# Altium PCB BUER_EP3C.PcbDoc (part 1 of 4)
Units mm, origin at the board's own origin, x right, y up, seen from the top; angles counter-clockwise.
Board outline 150 x 80 mm, 2 copper layers (Top Layer, Bottom Layer), stack 1.571 mm thick; 295 components, 180 nets, 1344 pads, 488 vias.
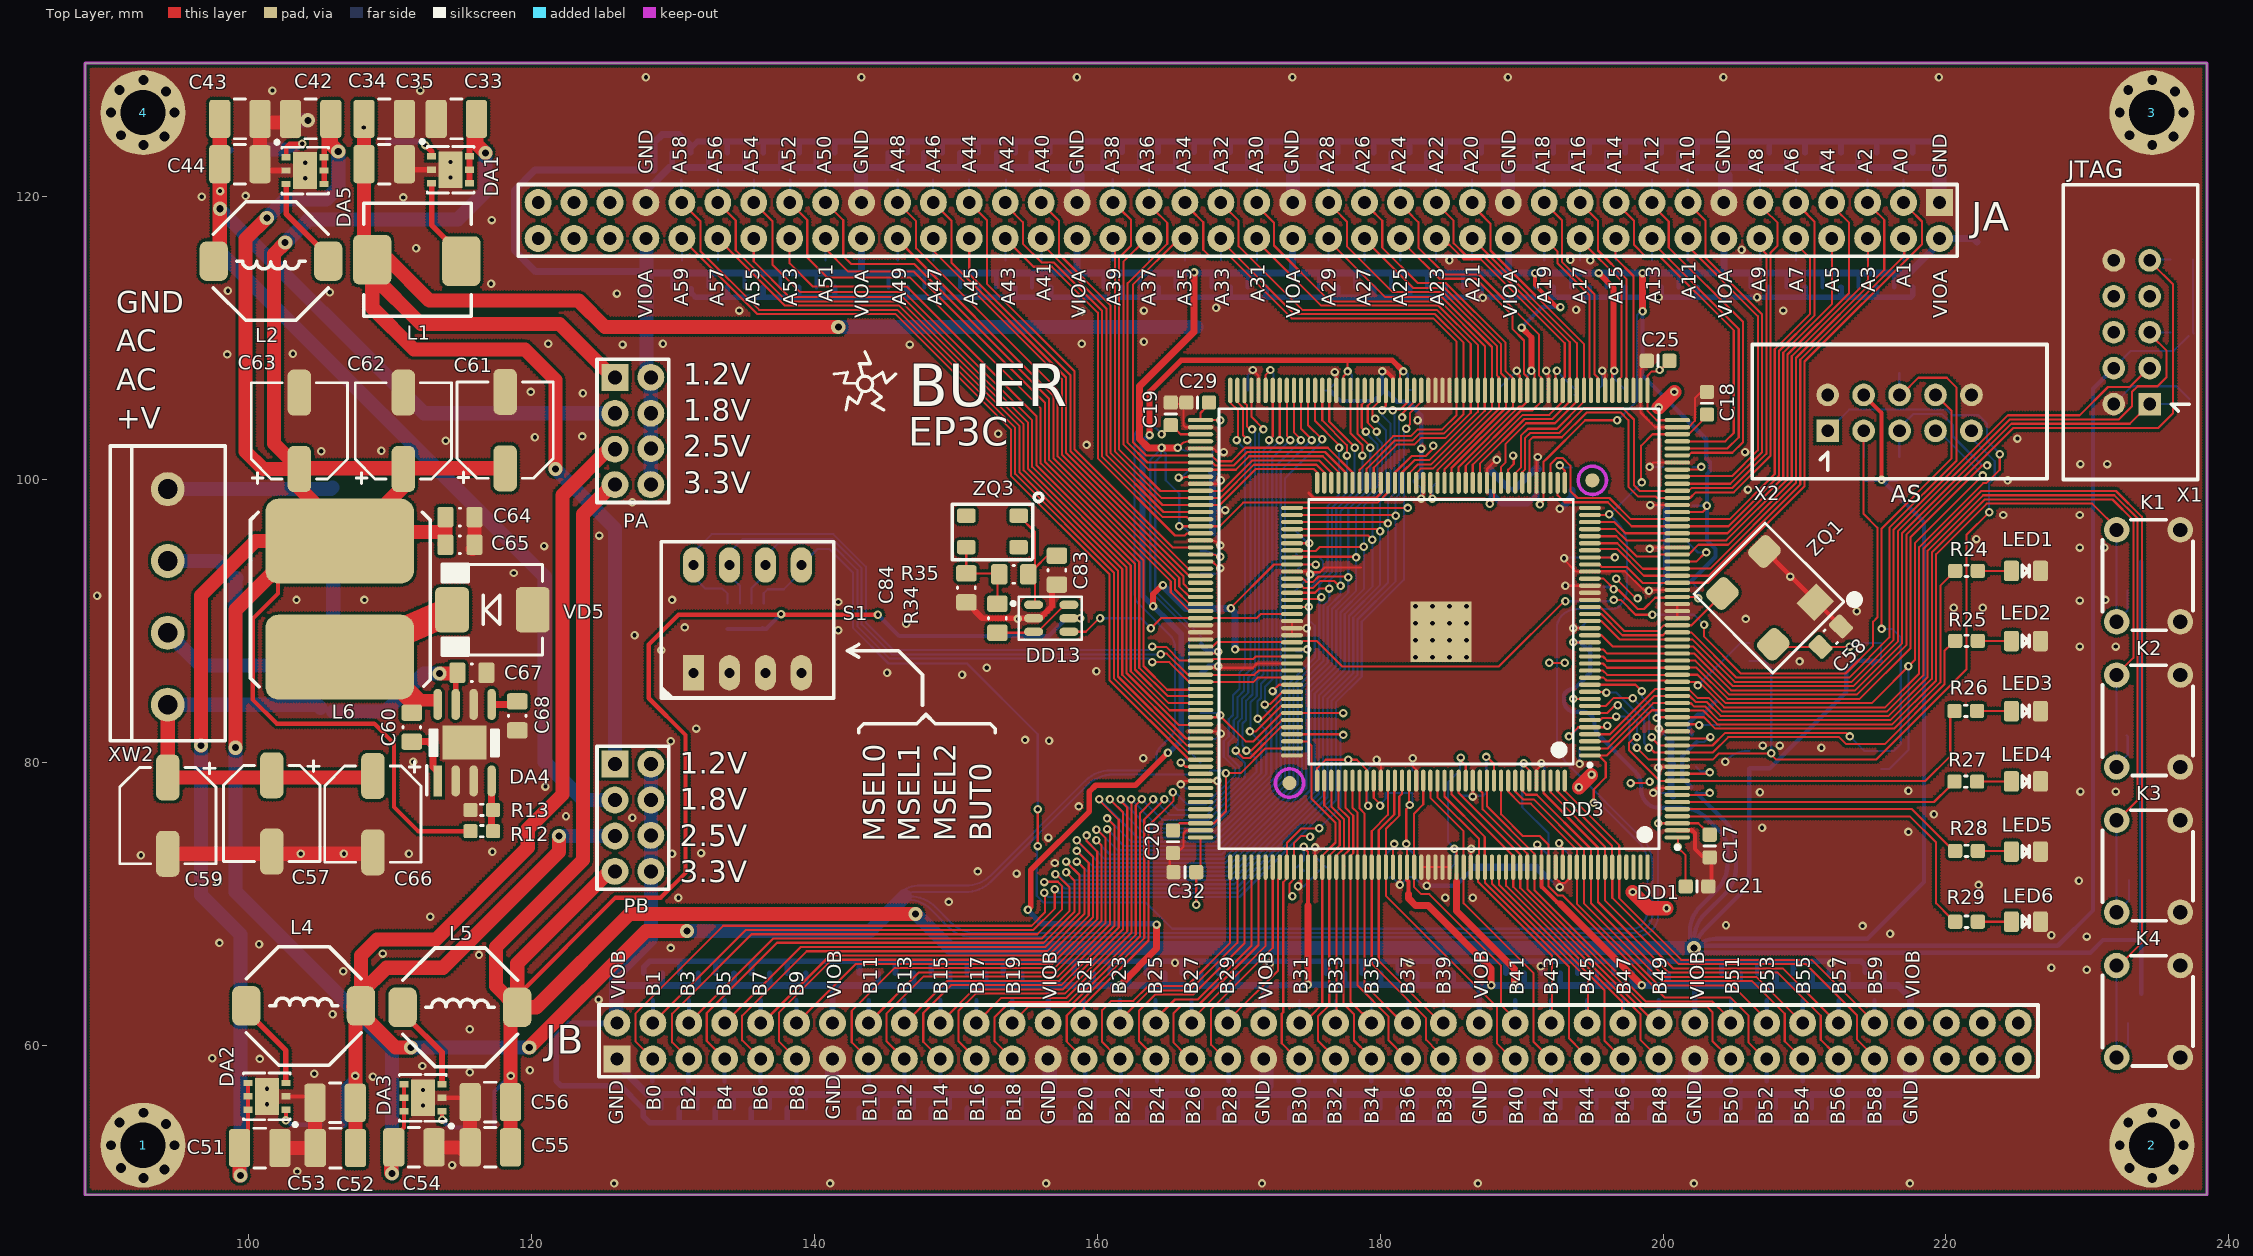
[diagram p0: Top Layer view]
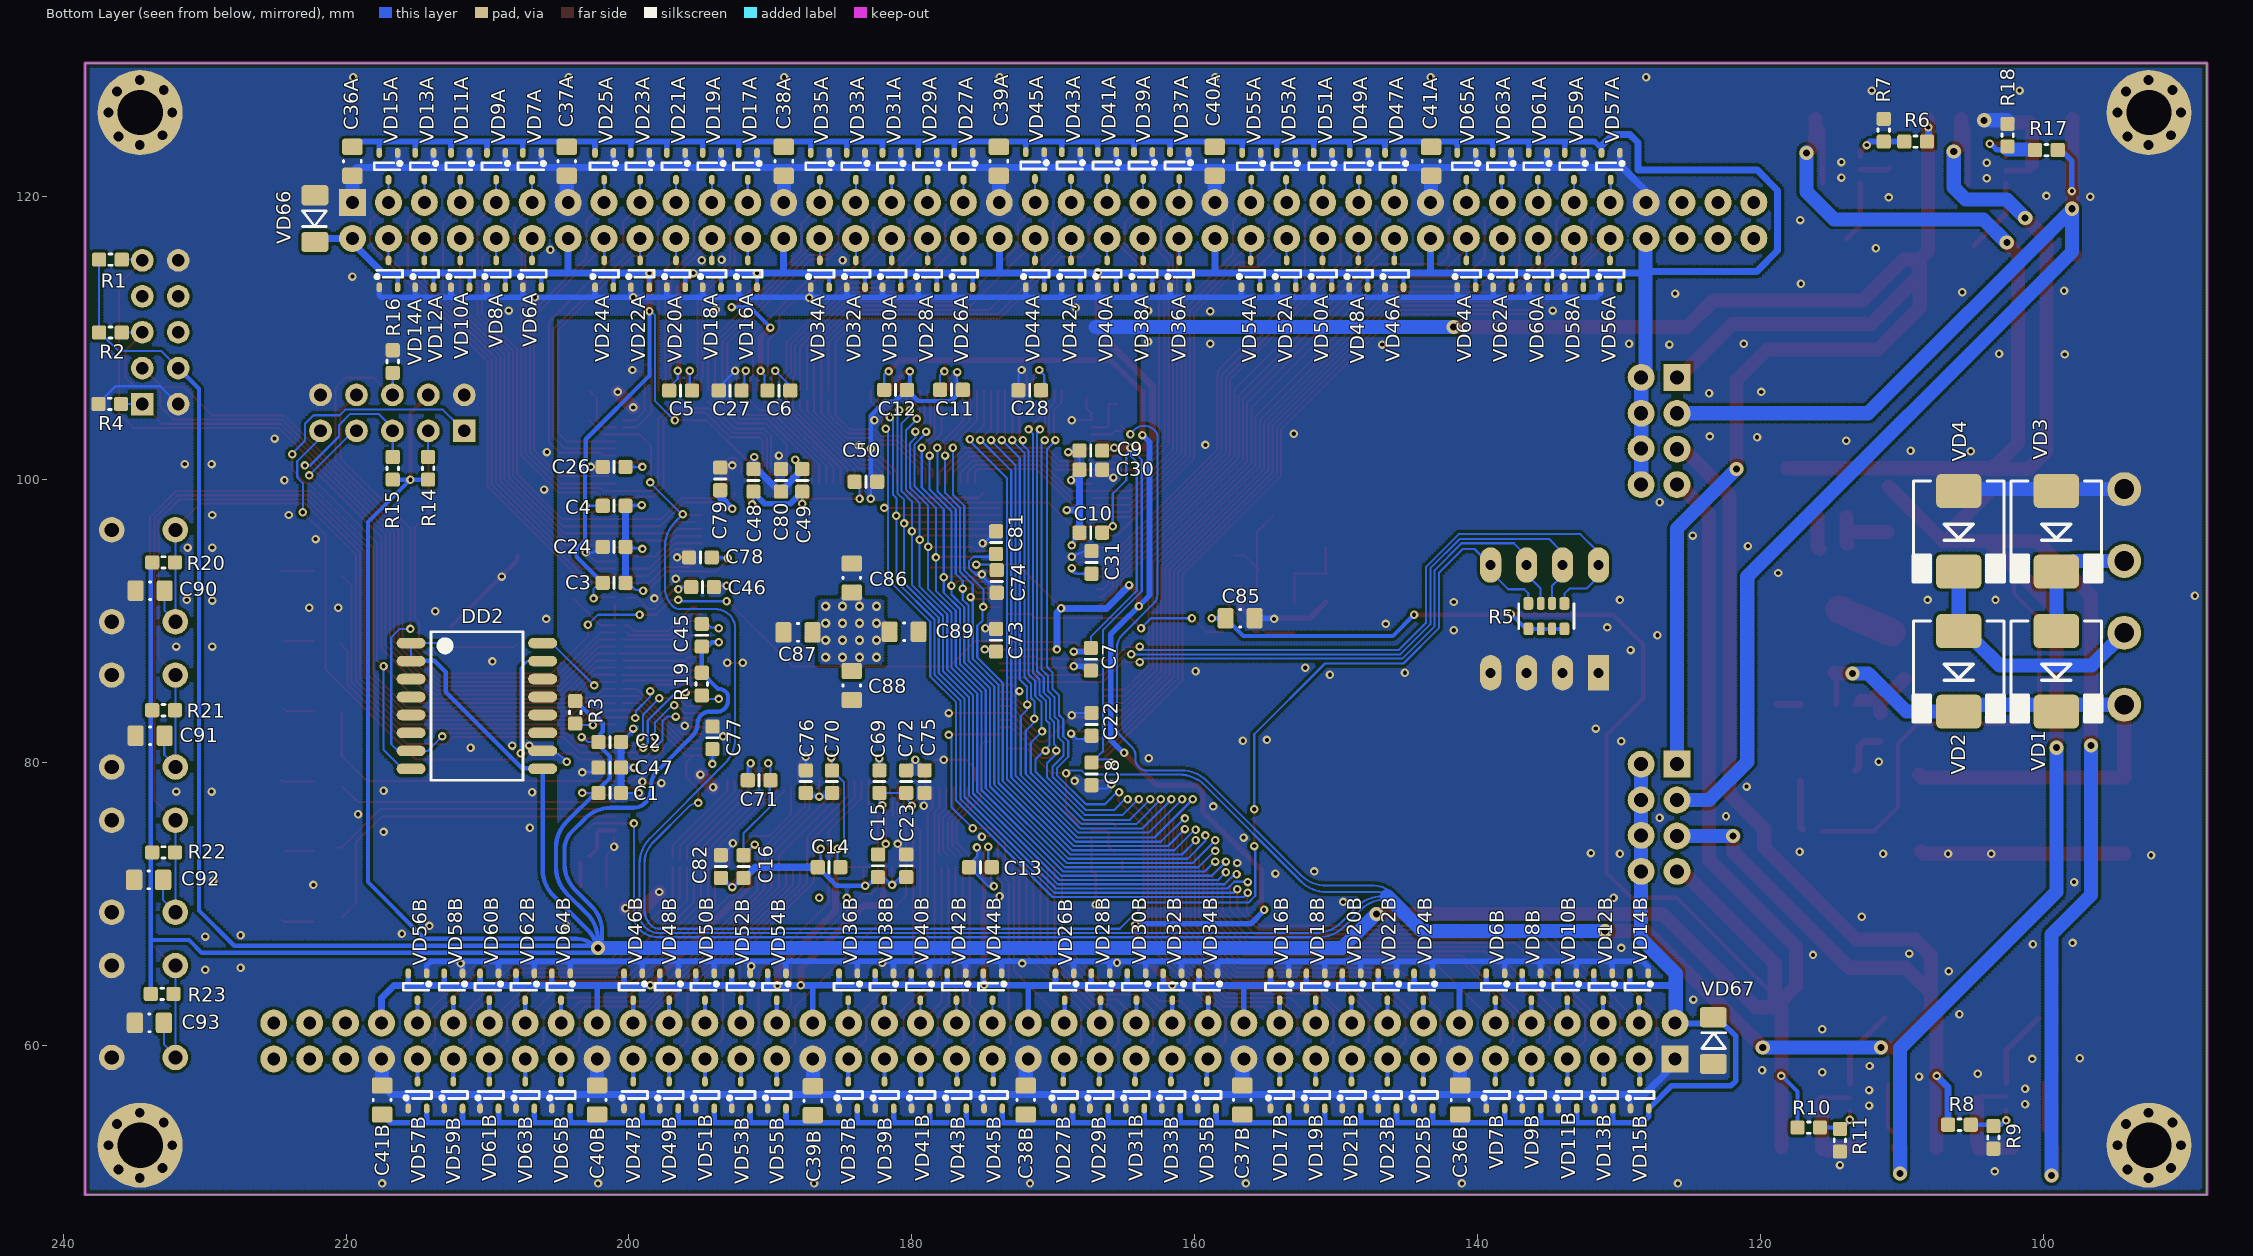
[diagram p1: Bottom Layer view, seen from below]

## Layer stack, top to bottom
Top Solder: solder mask 0.0102, Solder Resist, Dk 3.5
Top Layer: signal copper 0.0356
Dielectric1: core 1.5, FR-4, Dk 4.8
Bottom Layer: signal copper 0.0356
Bottom Solder: solder mask 0.0102, Solder Resist, Dk 3.5

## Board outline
88.45,49.45 88.45,129.45 238.45,129.45 238.45,49.45

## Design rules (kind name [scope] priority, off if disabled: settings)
Clearance Clearance_POLY [InPolygon] p1: gap=0.2
Clearance [All] p2: gap=0.15
ComponentClearance ComponentClearance_1 [InComponent('DD1') vs InComponent('DD3')] p1: gap=0 collisioncheckmode=3 verticalgap=0 showdistances=FALSE
ComponentClearance [All] p2: gap=0.254 collisioncheckmode=3 verticalgap=0.254 showdistances=FALSE
HoleSize [All] p1: absolutevalues=TRUE maxlimit=10 minlimit=0.3 maxpercent=80.000 minpercent=20.000
MinimumSolderMaskSliver MinimumSolderMaskSliver_1 [InComponent('1','2','3','4')] p1: minsoldermaskwidth=0
MinimumSolderMaskSliver [All] p2: minsoldermaskwidth=0.03
PlaneConnect [All] p1: planeconnectstyle=Direct reliefexpansion=0.508 reliefentries=4 reliefconductorwidth=0.254 reliefairgap=0.254
PolygonConnect [All] p1: connectstyle=Direct reliefconductorwidth=0.254 reliefentries=4 polygonreliefangle="90 Angle" airgapwidth=0.254
RoutingVias [All] p1: holewidth=0.5 width=1.3 viastyle="Through Hole" minholewidth=0.3 minwidth=0.6 maxholewidth=5 maxwidth=10
SilkToSilkClearance [All] p1: silktosilkclearance=0
SilkToSolderMaskClearance SilkscreenOverComponentPads [IsPad] p1: minsilkscreentomaskgap=0 clearancetoexposedcopper=TRUE
SolderMaskExpansion [All] p1: expansion=0.102
Width [All] p1: maxlimit=2 minlimit=0.15 preferedwidth=0.25
23 further rules are at their usual default settings.

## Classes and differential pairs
net class LED[0..5]: LED0 LED1 LED2 LED3 LED4 LED5
component class F: C42 C43 C44 DA5 L2 R17 R18
component class S: C60 C61 C62 C63 C64 C65 C66 C67 C68 DA4 L6 R12 R13 VD5
component class D: C33 C34 C35 DA1 L1 R6 R7
component class H: C54 C55 C56 DA3 L5 R10 R11
component class G: C51 C52 C53 DA2 L4 R8 R9
component class 0: DD1 R3
component class Main: 1 2 3 4 C58 C83 C84 C85 C90 C91 C92 C93 DD2 DD13 K1 K2 K3 K4 LED1 LED2 LED3 LED4 LED5 LED6 R1 R2 R4 R5 R14 R15 R16 R20 R21 R22 R23 R24 R25 R26 R27 R28 R29 R34 R35 S1 X1 X2 ZQ1 ZQ3
component class 3: C1 C2 C3 C4 C5 C6 C7 C8 C9 C10 C11 C12 C13 C14 C15 C16 C17 C18 C19 C20 C21 C22 C23 C24 C25 C26 C27 C28 C29 C30 C31 C32 C45 C46 C47 C48 C49 C50 C57 C59 C69 C70 C71 C72 C73 C74 C75 C76 C77 C78 C79 C80 C81 C82 C86 C87 C88 C89 PA PB VD1 VD2 VD3 VD4 XW2
component class A: JA VD66
net class A[0..59]: A0 A1 A2 A3 A4 A5 A6 A7 A8 A9 A10 A11 A12 A13 A14 A15 A16 A17 A18 A19 A20 A21 A22 A23 A24 A25 A26 A27 A28 A29 A30 A31 A32 A33 A34 A35 A36 A37 A38 A39 A40 A41 A42 A43 A44 A45 A46 A47 A48 A49 A50 A51 A52 A53 A54 A55 A56 A57 A58 A59
component class B: JB VD67
net class B[0..59]: B0 B1 B2 B3 B4 B5 B6 B7 B8 B9 B10 B11 B12 B13 B14 B15 B16 B17 B18 B19 B20 B21 B22 B23 B24 B25 B26 B27 B28 B29 B30 B31 B32 B33 B34 B35 B36 B37 B38 B39 B40 B41 B42 B43 B44 B45 B46 B47 B48 B49 B50 B51 B52 B53 B54 B55 B56 B57 B58 B59
channel class "10pin ESD protect_1": 11 12
channel class "10pin ESD protect_2": 21 22
channel class "10pin ESD protect_3": 31 32
channel class "10pin ESD protect_4": 41 42
channel class "10pin ESD protect_5": 51 52
channel class "10pin ESD protect_6": 61 62
component class 1A: C36A VD6A VD7A VD8A VD9A VD10A VD11A VD12A VD13A VD14A VD15A
component class 1B: C36B VD6B VD7B VD8B VD9B VD10B VD11B VD12B VD13B VD14B VD15B
component class 2A: C37A VD16A VD17A VD18A VD19A VD20A VD21A VD22A VD23A VD24A VD25A
component class 2B: C37B VD16B VD17B VD18B VD19B VD20B VD21B VD22B VD23B VD24B VD25B
component class 3A: C38A VD26A VD27A VD28A VD29A VD30A VD31A VD32A VD33A VD34A VD35A
component class 3B: C38B VD26B VD27B VD28B VD29B VD30B VD31B VD32B VD33B VD34B VD35B
component class 4A: C39A VD36A VD37A VD38A VD39A VD40A VD41A VD42A VD43A VD44A VD45A
component class 4B: C39B VD36B VD37B VD38B VD39B VD40B VD41B VD42B VD43B VD44B VD45B
component class 5A: C40A VD46A VD47A VD48A VD49A VD50A VD51A VD52A VD53A VD54A VD55A
component class 5B: C40B VD46B VD47B VD48B VD49B VD50B VD51B VD52B VD53B VD54B VD55B
component class 6A: C41A VD56A VD57A VD58A VD59A VD60A VD61A VD62A VD63A VD64A VD65A
component class 6B: C41B VD56B VD57B VD58B VD59B VD60B VD61B VD62B VD63B VD64B VD65B
net class MSEL[0..2]: MSEL0 MSEL1 MSEL2
component class 1: DD3 R19
net class BUT[0..3]: BUT0 BUT1 BUT2 BUT3

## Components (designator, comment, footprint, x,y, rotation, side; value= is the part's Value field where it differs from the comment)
1 "M3" M3 92.581,52.947 r90 top
2 "M3" M3 234.581,52.947 r90 top
3 "M3" M3 234.581,125.947 r90 top
4 "M3" M3 92.581,125.947 r90 top
C1 "100нФ 50 В 10% 0603 X7R" C0603 201.35,77.85 r180 bottom
C2 "100нФ 50 В 10% 0603 X7R" C0603 201.35,81.45 r180 bottom
C3 "100нФ 50 В 10% 0603 X7R" C0603 201.05,92.7 r180 bottom
C4 "100нФ 50 В 10% 0603 X7R" C0603 201.05,98.15 r180 bottom
C5 "100нФ 50 В 10% 0603 X7R" C0603 196.35,106.3 r180 bottom
C6 "100нФ 50 В 10% 0603 X7R" C0603 189.4,106.3 r180 bottom
C7 "100нФ 50 В 10% 0603 X7R" C0603 167.35,87.3 r270 bottom
C8 "100нФ 50 В 10% 0603 X7R" C0603 167.3,79.2 r270 bottom
C9 "100нФ 50 В 10% 0603 X7R" C0603 167.35,102.05 r0 bottom
C10 "100нФ 50 В 10% 0603 X7R" C0603 167.35,96.25 r0 bottom
C11 "100нФ 50 В 10% 0603 X7R" C0603 177.2,106.35 r180 bottom
C12 "100нФ 50 В 10% 0603 X7R" C0603 181.152,106.343 r180 bottom
C13 "100нФ 50 В 10% 0603 X7R" C0603 175.15,72.6 r0 bottom
C14 "100нФ 50 В 10% 0603 X7R" C0603 185.85,72.6 r0 bottom
C15 "100нФ 50 В 10% 0603 X7R" C0603 182.4,72.7 r270 bottom
C16 "100нФ 50 В 10% 0603 X7R" C0603 191.9,72.65 r270 bottom
C17 "100нФ 50 В 10% 0603 X7R" C0603 203.3,74.1 r270 top
C18 "100нФ 50 В 10% 0603 X7R" C0603 203.1,105.4 r90 top
C19 "100нФ 50 В 10% 0603 X7R" C0603 165.2,104.65 r90 top
C20 "100нФ 50 В 10% 0603 X7R" C0603 165.35,74.4 r270 top
C21 "100нФ 50 В 10% 0603 X7R" C0603 202.4,71.25 r0 top
C22 "100нФ 50 В 10% 0603 X7R" C0603 167.3,82.7 r270 bottom
C23 "100нФ 50 В 10% 0603 X7R" C0603 180.4,72.7 r270 bottom
C24 "100нФ 50 В 10% 0603 X7R" C0603 201.05,95.25 r180 bottom
C25 "100нФ 50 В 10% 0603 X7R" C0603 199.65,108.4 r180 top
C26 "100нФ 50 В 10% 0603 X7R" C0603 201.05,100.9 r180 bottom
C27 "100нФ 50 В 10% 0603 X7R" C0603 192.85,106.3 r180 bottom
C28 "100нФ 50 В 10% 0603 X7R" C0603 171.67,106.315 r180 bottom
C29 "100нФ 50 В 10% 0603 X7R" C0603 167.1,105.45 r180 top
C30 "100нФ 50 В 10% 0603 X7R" C0603 167.35,100.7 r0 bottom
C31 "100нФ 50 В 10% 0603 X7R" C0603 167.3,94.15 r270 bottom
C32 "100нФ 50 В 10% 0603 X7R" C0603 166.2,72.25 r180 top
C33 "22 мкФ 20% 16 В 1210 X7R" C1210 114.7,125.5 r180 top
C34 "22 мкФ 20% 16 В 1210 X7R" C1210 109.6,125.5 r0 top
C35 "22 мкФ 20% 16 В 1210 X7R" C1210 109.6,122.3 r0 top
C36A "470нФ 10% 50 В" C0805 219.55,122.5 r270 bottom (schematic designator C36)
C36B "470нФ 10% 50 В" C0805 141.25,56.15 r90 bottom (schematic designator C36)
C37A "470нФ 10% 50 В" C0805 204.4,122.5 r270 bottom (schematic designator C37)
C37B "470нФ 10% 50 В" C0805 156.65,56.15 r90 bottom (schematic designator C37)
C38A "470нФ 10% 50 В" C0805 189.05,122.5 r270 bottom (schematic designator C38)
C38B "470нФ 10% 50 В" C0805 171.95,56.15 r90 bottom (schematic designator C38)
C39A "470нФ 10% 50 В" C0805 173.85,122.5 r270 bottom (schematic designator C39)
C39B "470нФ 10% 50 В" C0805 187,56.1 r90 bottom (schematic designator C39)
C40A "470нФ 10% 50 В" C0805 158.6,122.5 r270 bottom (schematic designator C40)
C40B "470нФ 10% 50 В" C0805 202.25,56.15 r90 bottom (schematic designator C40)
C41A "470нФ 10% 50 В" C0805 143.3,122.5 r270 bottom (schematic designator C41)
C41B "470нФ 10% 50 В" C0805 217.45,56.15 r90 bottom (schematic designator C41)
C42 "22 мкФ 20% 16 В 1210 X7R" C1210 104.4,125.5 r180 top
C43 "22 мкФ 20% 16 В 1210 X7R" C1210 99.4,125.5 r0 top
C44 "22 мкФ 20% 16 В 1210 X7R" C1210 99.4,122.3 r0 top
C45 "100нФ 50 В 10% 0603 X7R" C0603 194.85,89 r90 bottom
C46 "100нФ 50 В 10% 0603 X7R" C0603 194.8,92.4 r180 bottom
C47 "100нФ 50 В 10% 0603 X7R" C0603 201.35,79.65 r180 bottom
C48 "100нФ 50 В 10% 0603 X7R" C0603 191.2,99.95 r90 bottom
C49 "100нФ 50 В 10% 0603 X7R" C0603 187.75,99.95 r90 bottom
C50 "100нФ 50 В 10% 0603 X7R" C0603 183.25,99.85 r180 bottom
C51 "22 мкФ 20% 16 В 1210 X7R" C1210 100.8,52.75 r0 top
C52 "22 мкФ 20% 16 В 1210 X7R" C1210 106.125,55.95 r180 top
C53 "22 мкФ 20% 16 В 1210 X7R" C1210 106.15,52.75 r180 top
C54 "22 мкФ 20% 16 В 1210 X7R" C1210 111.7,52.8 r0 top
C55 "22 мкФ 20% 16 В 1210 X7R" C1210 117.101,52.8 r180 top
C56 "22 мкФ 20% 16 В 1210 X7R" C1210 117.1,56 r180 top
C57 "100мкФ 35В 6.3x8" ELCAP_SMD_6.3x8 101.65,76.4 r270 top
C58 "470нФ 10% 50 В" C0805 211.85,88.9 r45 top
C59 "100мкФ 35В 6.3x8" ELCAP_SMD_6.3x8 94.3,76.25 r270 top
C60 "10нФ 10% 50 В" C0805 111.55,82.5 r90 top
C61 "220мкФ 16В 6.3x8" ELCAP_SMD_6.3x8 118.15,103.5 r90 top
C62 "220мкФ 16В 6.3x8" ELCAP_SMD_6.3x8 110.95,103.45 r90 top
C63 "220мкФ 16В 6.3x8" ELCAP_SMD_6.3x8 103.6,103.45 r90 top
C64 "470нФ 10% 50 В" C0805 114.95,97.35 r0 top
C65 "10нФ 10% 50 В" C0805 114.95,95.4 r0 top
C66 "100мкФ 35В 6.3x8" ELCAP_SMD_6.3x8 108.8,76.35 r270 top
C67 "470нФ 10% 50 В" C0805 115.8,86.35 r0 top
C68 "470нФ 10% 50 В" C0805 119,83.3 r270 top
C69 "100нФ 50 В 10% 0603 X7R" C0603 182.3,78.65 r90 bottom
C70 "100нФ 50 В 10% 0603 X7R" C0603 185.65,78.65 r270 bottom
C71 "100нФ 50 В 10% 0603 X7R" C0603 190.8,78.75 r0 bottom
C72 "100нФ 50 В 10% 0603 X7R" C0603 180.4,78.65 r90 bottom
C73 "100нФ 50 В 10% 0603 X7R" C0603 174.05,88.65 r90 bottom
C74 "100нФ 50 В 10% 0603 X7R" C0603 174,92.8 r270 bottom
C75 "100нФ 50 В 10% 0603 X7R" C0603 179.1,78.65 r90 bottom
C76 "100нФ 50 В 10% 0603 X7R" C0603 187.5,78.65 r270 bottom
C77 "100нФ 50 В 10% 0603 X7R" C0603 194.1,81.75 r270 bottom
C78 "100нФ 50 В 10% 0603 X7R" C0603 194.95,94.5 r180 bottom
C79 "100нФ 50 В 10% 0603 X7R" C0603 193.55,100.05 r270 bottom
C80 "100нФ 50 В 10% 0603 X7R" C0603 189.25,99.95 r270 bottom
C81 "100нФ 50 В 10% 0603 X7R" C0603 174.05,95.55 r270 bottom
C82 "100нФ 50 В 10% 0603 X7R" C0603 193.5,72.65 r270 bottom
C83 "27пФ  5%  50В 0805 NPO" C0805 157.15,93.6 r270 top
C84 "27пФ  5%  50В 0805 NPO" C0805 150.75,92.35 r270 top
C85 "470нФ 10% 50 В" C0805 156.8,90.2 r180 bottom
C86 "470нФ 10% 50 В" C0805 184.25,93.05 r270 bottom
C87 "470нФ 10% 50 В" C0805 188.05,89.2 r180 bottom
C88 "470нФ 10% 50 В" C0805 184.25,85.45 r90 bottom
C89 "470нФ 10% 50 В" C0805 180.55,89.25 r0 bottom
C90 "10нФ 10% 50 В" C0805 233.85,92.15 r0 bottom
C91 "10нФ 10% 50 В" C0805 233.85,81.9 r0 bottom
C92 "10нФ 10% 50 В" C0805 233.95,71.7 r0 bottom
C93 "10нФ 10% 50 В" C0805 233.9,61.6 r0 bottom
DA1 "NCP1597A" DFN6 114.29,121.9 r270 top
DA2 "NCP1597A" DFN6 101.31,56.4 r90 top
DA3 "NCP1597A" DFN6 112.34,56.3 r90 top
DA4 "TPS5450DDA" HSOP8 115.285,81.405 r90 top
DA5 "NCP1597A" DFN6 104.01,121.85 r270 top
DD1 "EP3C16Q240C8N" PQFP240_N 184.156,89.457 r180 top
DD2 "EPCS16SI16N" SO-16W 210.75,84 r270 bottom
DD3 "EP3C10E144C8" EQFP-144 184.3,89.25 r180 top
DD13 "74LVC2G04" SOT-23-6 156.75,90.2 r0 top
JA "PLD-80" "HEADER 2X40" 219.54,119.59 r180 top
JB "PLD-80" "HEADER 2X40" 126.05,59.05 r0 top
K1 "SWT-2/5 (0650HIM-160G-G)" SWT-2/5 234.35,93.25 r270 top
K2 "SWT-2/5 (0650HIM-160G-G)" SWT-2/5 234.35,82.983 r270 top
K3 "SWT-2/5 (0650HIM-160G-G)" SWT-2/5 234.35,72.717 r270 top
K4 "SWT-2/5 (0650HIM-160G-G)" SWT-2/5 234.35,62.45 r270 top
L1 "DR73-3R3-R" DR73 111.95,115.45 r180 top
L2 "CDRH8D43NP-6R8NC" CDRH8D43 105.65,115.45 r180 top
L4 "CDRH8D43NP-6R8NC" CDRH8D43 99.85,62.8 r0 top
L5 "CDRH8D43NP-6R8NC" CDRH8D43 110.9,62.7 r0 top
L6 "DR127-150-R" DR127 106.55,91.55 r90 top
LED1 "FYLS-0805UWC" LED0805W 225.65,93.55 r0 top
LED2 "FYLS-0805UWC" LED0805W 225.65,88.59 r0 top
LED3 "FYLS-0805UWC" LED0805W 225.65,83.63 r0 top
LED4 "FYLS-0805UWC" LED0805W 225.65,78.67 r0 top
LED5 "FYLS-0805UWC" LED0805W 225.65,73.71 r0 top
LED6 "FYLS-0805UWC" LED0805W 225.65,68.751 r0 top
PA "PLD-8" "HEADER 2X4" 128.45,107.23 r270 top
PB "PLD-8" "HEADER 2X4" 128.45,79.89 r270 top
R1 "10 кОм 0603 5%" R0603 236.65,115.55 r0 bottom
R2 "10 кОм 0603 5%" R0603 236.65,110.4 r0 bottom
R3 "10 кОм 0603 5%" R0603 203.8,83.55 r90 bottom
R4 "10 кОм 0603 5%" R0603 236.7,105.35 r0 bottom
R5 "2.2 кОм 4D03" 4D03 135.15,90.35 r270 bottom
R6 "1.0 кОм 0603 5%" R0603 109.05,123.9 r180 bottom
R7 "2.0 кОм 0603 5%" R0603 111.3,124.7 r270 bottom
R8 "5.1 кОм 0603 5%" R0603 105.95,54.4 r0 bottom
R9 "2.4 кОм 0603 5%" R0603 103.55,53.5 r90 bottom
R10 "7.5 кОм 0603 5%" R0603 116.6,54.2 r0 bottom
R11 "2.4 кОм 0603 5%" R0603 114.4,53.3 r90 bottom
R12 "6.8 кОм 0603 5%" R0603 116.5,75.15 r180 top
R13 "2.2 кОм 0603 5%" R0603 116.5,76.65 r0 top
R14 "10 кОм 0603 5%" R0603 214.2,100.8 r270 bottom
R15 "10 кОм 0603 5%" R0603 216.7,100.8 r270 bottom
R16 "10 кОм 0603 5%" R0603 216.7,108.35 r270 bottom
R17 "1.5 кОм 0603 5%" R0603 99.8,123.3 r180 bottom
R18 "1.2 кОм 0603 5%" R0603 102.55,124.35 r270 bottom
R19 "10 кОм 0603 5%" R0603 194.85,85.55 r90 bottom
R20 "1.0 кОм 0603 5%" R0603 232.9,94.15 r0 bottom
R21 "1.0 кОм 0603 5%" R0603 232.9,83.7 r0 bottom
R22 "1.0 кОм 0603 5%" R0603 232.9,73.65 r0 bottom
R23 "1.0 кОм 0603 5%" R0603 233,63.65 r0 bottom
R24 "1.0 кОм 0603 5%" R0603 221.45,93.55 r180 top
R25 "1.0 кОм 0603 5%" R0603 221.45,88.6 r180 top
R26 "1.0 кОм 0603 5%" R0603 221.4,83.65 r180 top
R27 "1.0 кОм 0603 5%" R0603 221.4,78.65 r180 top
R28 "1.0 кОм 0603 5%" R0603 221.45,73.75 r180 top
R29 "1.0 кОм 0603 5%" R0603 221.45,68.75 r180 top
R34 "200 Ом 0805 5%" R0805 152.95,90.2 r270 top
R35 "3.9 МОм 0805 5%" R0805 154.1,93.3 r180 top
S1 "SWD1-4" DIPSW-4 135.275,89.771 r0 top
VD1 "MBRS540T3G" "DO-214AB (SMC)" 99.1,86.45 r270 bottom
VD2 "MBRS540T3G" "DO-214AB (SMC)" 106,86.45 r270 bottom
VD3 "MBRS540T3G" "DO-214AB (SMC)" 99.1,96.35 r270 bottom
VD4 "MBRS540T3G" "DO-214AB (SMC)" 106,96.35 r270 bottom
VD5 "MBRS540T3G" "DO-214AB (SMC)" 117.25,90.8 r180 top
VD6A "BAT54SWT1G" SC-70 206.85,114.55 r90 bottom (schematic designator VD6)
VD6B "BAT54SWT1G" SC-70 138.75,64.15 r270 bottom (schematic designator VD6)
VD7A "BAT54SWT1G" SC-70 206.85,122.15 r270 bottom (schematic designator VD7)
VD7B "BAT54SWT1G" SC-70 138.75,56.5 r90 bottom (schematic designator VD7)
VD8A "BAT54SWT1G" SC-70 209.387,114.55 r90 bottom (schematic designator VD8)
VD8B "BAT54SWT1G" SC-70 136.212,64.15 r270 bottom (schematic designator VD8)
VD9A "BAT54SWT1G" SC-70 209.387,122.15 r270 bottom (schematic designator VD9)
VD9B "BAT54SWT1G" SC-70 136.2,56.5 r90 bottom (schematic designator VD9)
VD10A "BAT54SWT1G" SC-70 211.925,114.55 r90 bottom (schematic designator VD10)
VD10B "BAT54SWT1G" SC-70 133.675,64.15 r270 bottom (schematic designator VD10)
VD11A "BAT54SWT1G" SC-70 211.925,122.15 r270 bottom (schematic designator VD11)
VD11B "BAT54SWT1G" SC-70 133.65,56.5 r90 bottom (schematic designator VD11)
VD12A "BAT54SWT1G" SC-70 214.462,114.55 r90 bottom (schematic designator VD12)
VD12B "BAT54SWT1G" SC-70 131.137,64.15 r270 bottom (schematic designator VD12)
VD13A "BAT54SWT1G" SC-70 214.462,122.15 r270 bottom (schematic designator VD13)
VD13B "BAT54SWT1G" SC-70 131.1,56.5 r90 bottom (schematic designator VD13)
VD14A "BAT54SWT1G" SC-70 217,114.55 r90 bottom (schematic designator VD14)
VD14B "BAT54SWT1G" SC-70 128.6,64.15 r270 bottom (schematic designator VD14)
VD15A "BAT54SWT1G" SC-70 217,122.15 r270 bottom (schematic designator VD15)
VD15B "BAT54SWT1G" SC-70 128.55,56.5 r90 bottom (schematic designator VD15)
VD16A "BAT54SWT1G" SC-70 191.6,114.55 r90 bottom (schematic designator VD16)
VD16B "BAT54SWT1G" SC-70 154,64.15 r270 bottom (schematic designator VD16)
VD17A "BAT54SWT1G" SC-70 191.6,122.15 r270 bottom (schematic designator VD17)
VD17B "BAT54SWT1G" SC-70 154,56.5 r90 bottom (schematic designator VD17)
VD18A "BAT54SWT1G" SC-70 194.137,114.55 r90 bottom (schematic designator VD18)
VD18B "BAT54SWT1G" SC-70 151.463,64.15 r270 bottom (schematic designator VD18)
VD19A "BAT54SWT1G" SC-70 194.137,122.15 r270 bottom (schematic designator VD19)
VD19B "BAT54SWT1G" SC-70 151.462,56.5 r90 bottom (schematic designator VD19)
VD20A "BAT54SWT1G" SC-70 196.675,114.55 r90 bottom (schematic designator VD20)
VD20B "BAT54SWT1G" SC-70 148.925,64.15 r270 bottom (schematic designator VD20)
VD21A "BAT54SWT1G" SC-70 196.675,122.15 r270 bottom (schematic designator VD21)
VD21B "BAT54SWT1G" SC-70 148.925,56.5 r90 bottom (schematic designator VD21)
VD22A "BAT54SWT1G" SC-70 199.212,114.55 r90 bottom (schematic designator VD22)
VD22B "BAT54SWT1G" SC-70 146.387,64.15 r270 bottom (schematic designator VD22)
VD23A "BAT54SWT1G" SC-70 199.212,122.15 r270 bottom (schematic designator VD23)
VD23B "BAT54SWT1G" SC-70 146.387,56.5 r90 bottom (schematic designator VD23)
VD24A "BAT54SWT1G" SC-70 201.75,114.55 r90 bottom (schematic designator VD24)
VD24B "BAT54SWT1G" SC-70 143.85,64.15 r270 bottom (schematic designator VD24)
VD25A "BAT54SWT1G" SC-70 201.75,122.15 r270 bottom (schematic designator VD25)
VD25B "BAT54SWT1G" SC-70 143.85,56.5 r90 bottom (schematic designator VD25)
VD26A "BAT54SWT1G" SC-70 176.35,114.55 r90 bottom (schematic designator VD26)
VD26B "BAT54SWT1G" SC-70 169.2,64.15 r270 bottom (schematic designator VD26)
VD27A "BAT54SWT1G" SC-70 176.35,122.15 r270 bottom (schematic designator VD27)
VD27B "BAT54SWT1G" SC-70 169.3,56.5 r90 bottom (schematic designator VD27)
VD28A "BAT54SWT1G" SC-70 178.887,114.55 r90 bottom (schematic designator VD28)
VD28B "BAT54SWT1G" SC-70 166.662,64.15 r270 bottom (schematic designator VD28)
VD29A "BAT54SWT1G" SC-70 178.887,122.15 r270 bottom (schematic designator VD29)
VD29B "BAT54SWT1G" SC-70 166.762,56.5 r90 bottom (schematic designator VD29)
VD30A "BAT54SWT1G" SC-70 181.425,114.55 r90 bottom (schematic designator VD30)
VD30B "BAT54SWT1G" SC-70 164.125,64.15 r270 bottom (schematic designator VD30)
VD31A "BAT54SWT1G" SC-70 181.425,122.15 r270 bottom (schematic designator VD31)
VD31B "BAT54SWT1G" SC-70 164.225,56.5 r90 bottom (schematic designator VD31)
VD32A "BAT54SWT1G" SC-70 183.962,114.55 r90 bottom (schematic designator VD32)
VD32B "BAT54SWT1G" SC-70 161.588,64.15 r270 bottom (schematic designator VD32)
VD33A "BAT54SWT1G" SC-70 183.962,122.15 r270 bottom (schematic designator VD33)
VD33B "BAT54SWT1G" SC-70 161.687,56.5 r90 bottom (schematic designator VD33)
VD34A "BAT54SWT1G" SC-70 186.5,114.55 r90 bottom (schematic designator VD34)
VD34B "BAT54SWT1G" SC-70 159.05,64.15 r270 bottom (schematic designator VD34)
VD35A "BAT54SWT1G" SC-70 186.5,122.15 r270 bottom (schematic designator VD35)
VD35B "BAT54SWT1G" SC-70 159.15,56.5 r90 bottom (schematic designator VD35)
VD36A "BAT54SWT1G" SC-70 161.1,114.55 r90 bottom (schematic designator VD36)
VD36B "BAT54SWT1G" SC-70 184.5,64.15 r270 bottom (schematic designator VD36)
VD37A "BAT54SWT1G" SC-70 161.1,122.2 r270 bottom (schematic designator VD37)
VD37B "BAT54SWT1G" SC-70 184.5,56.5 r90 bottom (schematic designator VD37)
VD38A "BAT54SWT1G" SC-70 163.65,114.55 r90 bottom (schematic designator VD38)
VD38B "BAT54SWT1G" SC-70 181.95,64.15 r270 bottom (schematic designator VD38)
VD39A "BAT54SWT1G" SC-70 163.65,122.2 r270 bottom (schematic designator VD39)
VD39B "BAT54SWT1G" SC-70 181.937,56.5 r90 bottom (schematic designator VD39)
VD40A "BAT54SWT1G" SC-70 166.2,114.55 r90 bottom (schematic designator VD40)
VD40B "BAT54SWT1G" SC-70 179.4,64.15 r270 bottom (schematic designator VD40)
VD41A "BAT54SWT1G" SC-70 166.2,122.2 r270 bottom (schematic designator VD41)
VD41B "BAT54SWT1G" SC-70 179.375,56.5 r90 bottom (schematic designator VD41)
VD42A "BAT54SWT1G" SC-70 168.75,114.55 r90 bottom (schematic designator VD42)
VD42B "BAT54SWT1G" SC-70 176.85,64.15 r270 bottom (schematic designator VD42)
VD43A "BAT54SWT1G" SC-70 168.75,122.2 r270 bottom (schematic designator VD43)
VD43B "BAT54SWT1G" SC-70 176.812,56.5 r90 bottom (schematic designator VD43)
VD44A "BAT54SWT1G" SC-70 171.3,114.55 r90 bottom (schematic designator VD44)
VD44B "BAT54SWT1G" SC-70 174.3,64.15 r270 bottom (schematic designator VD44)
VD45A "BAT54SWT1G" SC-70 171.3,122.2 r270 bottom (schematic designator VD45)
VD45B "BAT54SWT1G" SC-70 174.25,56.5 r90 bottom (schematic designator VD45)
VD46A "BAT54SWT1G" SC-70 145.9,114.55 r90 bottom (schematic designator VD46)
VD46B "BAT54SWT1G" SC-70 199.7,64.15 r270 bottom (schematic designator VD46)
VD47A "BAT54SWT1G" SC-70 145.9,122.15 r270 bottom (schematic designator VD47)
VD47B "BAT54SWT1G" SC-70 199.7,56.5 r90 bottom (schematic designator VD47)
VD48A "BAT54SWT1G" SC-70 148.437,114.55 r90 bottom (schematic designator VD48)
VD48B "BAT54SWT1G" SC-70 197.162,64.15 r270 bottom (schematic designator VD48)
VD49A "BAT54SWT1G" SC-70 148.4,122.15 r270 bottom (schematic designator VD49)
VD49B "BAT54SWT1G" SC-70 197.162,56.5 r90 bottom (schematic designator VD49)
VD50A "BAT54SWT1G" SC-70 150.975,114.55 r90 bottom (schematic designator VD50)
VD50B "BAT54SWT1G" SC-70 194.625,64.15 r270 bottom (schematic designator VD50)
VD51A "BAT54SWT1G" SC-70 150.95,122.15 r270 bottom (schematic designator VD51)
VD51B "BAT54SWT1G" SC-70 194.625,56.5 r90 bottom (schematic designator VD51)
VD52A "BAT54SWT1G" SC-70 153.512,114.55 r90 bottom (schematic designator VD52)
VD52B "BAT54SWT1G" SC-70 192.088,64.15 r270 bottom (schematic designator VD52)
VD53A "BAT54SWT1G" SC-70 153.55,122.15 r270 bottom (schematic designator VD53)
VD53B "BAT54SWT1G" SC-70 192.087,56.5 r90 bottom (schematic designator VD53)
VD54A "BAT54SWT1G" SC-70 156.05,114.55 r90 bottom (schematic designator VD54)
VD54B "BAT54SWT1G" SC-70 189.55,64.15 r270 bottom (schematic designator VD54)
VD55A "BAT54SWT1G" SC-70 156,122.15 r270 bottom (schematic designator VD55)
VD55B "BAT54SWT1G" SC-70 189.55,56.5 r90 bottom (schematic designator VD55)
VD56A "BAT54SWT1G" SC-70 130.65,114.55 r90 bottom (schematic designator VD56)
VD56B "BAT54SWT1G" SC-70 214.95,64.15 r270 bottom (schematic designator VD56)
VD57A "BAT54SWT1G" SC-70 130.6,122.15 r270 bottom (schematic designator VD57)
VD57B "BAT54SWT1G" SC-70 214.95,56.5 r90 bottom (schematic designator VD57)
VD58A "BAT54SWT1G" SC-70 133.187,114.55 r90 bottom (schematic designator VD58)
VD58B "BAT54SWT1G" SC-70 212.412,64.15 r270 bottom (schematic designator VD58)
VD59A "BAT54SWT1G" SC-70 133.2,122.15 r270 bottom (schematic designator VD59)
VD59B "BAT54SWT1G" SC-70 212.412,56.5 r90 bottom (schematic designator VD59)
VD60A "BAT54SWT1G" SC-70 135.725,114.55 r90 bottom (schematic designator VD60)
VD60B "BAT54SWT1G" SC-70 209.875,64.15 r270 bottom (schematic designator VD60)
VD61A "BAT54SWT1G" SC-70 135.75,122.15 r270 bottom (schematic designator VD61)
VD61B "BAT54SWT1G" SC-70 209.875,56.5 r90 bottom (schematic designator VD61)
VD62A "BAT54SWT1G" SC-70 138.262,114.55 r90 bottom (schematic designator VD62)
VD62B "BAT54SWT1G" SC-70 207.337,64.15 r270 bottom (schematic designator VD62)
VD63A "BAT54SWT1G" SC-70 138.3,122.15 r270 bottom (schematic designator VD63)
VD63B "BAT54SWT1G" SC-70 207.337,56.5 r90 bottom (schematic designator VD63)
VD64A "BAT54SWT1G" SC-70 140.8,114.55 r90 bottom (schematic designator VD64)
VD64B "BAT54SWT1G" SC-70 204.8,64.15 r270 bottom (schematic designator VD64)
VD65A "BAT54SWT1G" SC-70 140.8,122.15 r270 bottom (schematic designator VD65)
VD65B "BAT54SWT1G" SC-70 204.8,56.5 r90 bottom (schematic designator VD65)
VD66 "BZV55-C3V3" SOD-80 222.2,118.5 r270 bottom
VD67 "BZV55-C3V3" SOD-80 123.35,60.3 r90 bottom
X1 "BH-10" BH-10 234.4,105.34 r90 top
X2 "BH-10" BH-10 211.64,103.45 r0 top
XW2 "MKDSN 1.5/4-5.08" "MKDSN 1.5/4-5.08" 94.3,99.33 r270 top
ZQ1 "100.0 MHz KXO-V97" KXO-97 207.481,91.639 r135 top
ZQ3 "11.0592MHz KX-9A" KX-9A 152.45,96.25 r180 top

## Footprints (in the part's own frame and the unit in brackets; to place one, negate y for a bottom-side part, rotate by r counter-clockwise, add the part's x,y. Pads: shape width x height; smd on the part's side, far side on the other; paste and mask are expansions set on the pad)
4D03 [mm]
  rrect50% 0.9x0.7 smd mask+0.127: 1(-0.9,1.275) 4(-0.9,-1.275) 5(0.9,-1.275) 8(0.9,1.275)
  rrect50% 0.9x0.55 smd mask+0.127: 2(-0.9,0.4) 3(-0.9,-0.4) 6(0.9,-0.4) 7(0.9,0.4)
  silkscreen extent -0.87,-1.95 0.87,1.95, body extent -0.8,-1.6 0.8,1.6, height 0.6
BH-10 [mm]
  rect 1.6x1.6 hole 0.9: 1(0,0)
  round 1.6 hole 0.9: 2(0,2.54) 3(2.54,0) 4(2.54,2.54) 5(5.08,0) 6(5.08,2.54) 7(7.62,0) 8(7.62,2.54) 9(10.16,0) 10(10.16,2.54)
  silkscreen extent -5.33,-3.4 15.5,6.1, body extent -5.15,-3.3 15.35,6, height 9.1
C0603 [mm]
  rrect30% 1x1 smd: 1(-0.8,0) 2(0.8,0)
  silkscreen extent 0,-0.4 0,0.4, body extent -0.8,-0.4 0.8,0.4, height 0.3
C0805 [mm]
  rrect30% 1.15x1.45 smd: 1(-1.025,0) 2(1.025,0)
  silkscreen extent -0.05,-0.63 0.05,0.63, body extent -1,-0.6 1,0.65, height 0.78
C1210 [mm]
  rrect30% 1.5x2.7 smd: 1(-1.425,0) 2(1.425,0)
  silkscreen extent -0.4,-1.4 0.4,1.4, body extent -2.1,-1.4 2.1,1.3, height 0.95
CDRH8D43 [mm]
  rrect50% 2x2.8 smd: 1(0,0) 2(8.1,0)
  silkscreen extent 0,-4.19 8.13,4.19, body extent -0.57,-4 8.7,4, height 4.61
DFN6 [mm] "DFN6 3x3, 0.95P  CASE 506AH?01  ISSUE O"
  rect 0.45x0.63 smd: 1(-0.95,-1.34) 2(0,-1.34) 3(0.95,-1.34) 4(0.95,1.34) 5(0,1.34) 6(-0.95,1.34)
  rect 2.6x1.7 smd: 7(0,0)
  silkscreen extent -2.12,-2.12 1.65,1.65, body extent -1.5,-1.5 1.5,1.5, height 1
DIPSW-4 [mm]
  rect 1.5x2.5 hole 0.7: 1(-3.81,-3.429)
  oval 1.5x2.5 hole 0.7: 2(-1.27,-3.429) 3(1.27,-3.429) 4(3.81,-3.429) 5(3.81,4.19) 6(1.27,4.19) 7(-1.27,4.19) 8(-3.81,4.19)
  silkscreen extent -6.1,-5.21 6.1,5.84, body extent -5.72,-4.32 5.71,5.33, height 7.52
"DO-214AB (SMC)" [mm]
  rrect30% 2.4x3.2 smd: 1(-2.85,0) 2(2.85,0)
  silkscreen extent -3.55,-3.2 3.55,3.2, body extent -3.98,-2.9 3.97,3, height 2.3
DR73 [mm]
  rrect30% 2.7x3.5 smd: 1(-3.1,0) 2(3.2,-0.1)
  silkscreen extent -3.8,-4.1 3.8,3.9, body extent -3.8,-3.9 3.8,3.7, height 3.55
DR127 [mm]
  rrect30% 6x10.5 smd: 1(-4.1,0.1) 2(4.1,0.1)
  silkscreen extent -6.2,-6.3 6.15,6.4, body extent -6.45,-6.2 6.45,6.3, height 8.31
ELCAP_SMD_6.3x8 [mm]
  rrect50% 3.25x1.65 smd: 1(-2.7,0) 2(2.7,0)
  silkscreen extent -3.72,-3.4 3.4,3.4, body extent -3.55,-3.3 3.75,3.3, height 7.9
EQFP-144 [mm] "Thin QFP, 144-Leads, Body 20x20mm, Pitch 0.5mm, IPC High Density"
  oval 1.55x0.3 smd: 1(-10.525,8.75) 2(-10.525,8.25) 3(-10.525,7.75) 4(-10.525,7.25) 5(-10.525,6.75) 6(-10.525,6.25) 7(-10.525,5.75) 8(-10.525,5.25) 9(-10.525,4.75) 10(-10.525,4.25) 11(-10.525,3.75) 12(-10.525,3.25) 13(-10.525,2.75) 14(-10.525,2.25) 15(-10.525,1.75) 16(-10.525,1.25) 17(-10.525,0.75) 18(-10.525,0.25) 19(-10.525,-0.25) 20(-10.525,-0.75) 21(-10.525,-1.25) 22(-10.525,-1.75) 23(-10.525,-2.25) 24(-10.525,-2.75) 25(-10.525,-3.25) 26(-10.525,-3.75) 27(-10.525,-4.25) 28(-10.525,-4.75) 29(-10.525,-5.25) 30(-10.525,-5.75) 31(-10.525,-6.25) 32(-10.525,-6.75) 33(-10.525,-7.25) 34(-10.525,-7.75) 35(-10.525,-8.25) 36(-10.525,-8.75) 73(10.525,-8.75) 74(10.525,-8.25) 75(10.525,-7.75) 76(10.525,-7.25) 77(10.525,-6.75) 78(10.525,-6.25) 79(10.525,-5.75) 80(10.525,-5.25) 81(10.525,-4.75) 82(10.525,-4.25) 83(10.525,-3.75) 84(10.525,-3.25) 85(10.525,-2.75) 86(10.525,-2.25) 87(10.525,-1.75) 88(10.525,-1.25) 89(10.525,-0.75) 90(10.525,-0.25) 91(10.525,0.25) 92(10.525,0.75) 93(10.525,1.25) 94(10.525,1.75) 95(10.525,2.25) 96(10.525,2.75) 97(10.525,3.25) 98(10.525,3.75) 99(10.525,4.25) 100(10.525,4.75) 101(10.525,5.25) 102(10.525,5.75) 103(10.525,6.25) 104(10.525,6.75) 105(10.525,7.25) 106(10.525,7.75) 107(10.525,8.25) 108(10.525,8.75)
  oval 0.3x1.55 smd: 37(-8.75,-10.525) 38(-8.25,-10.525) 39(-7.75,-10.525) 40(-7.25,-10.525) 41(-6.75,-10.525) 42(-6.25,-10.525) 43(-5.75,-10.525) 44(-5.25,-10.525) 45(-4.75,-10.525) 46(-4.25,-10.525) 47(-3.75,-10.525) 48(-3.25,-10.525) 49(-2.75,-10.525) 50(-2.25,-10.525) 51(-1.75,-10.525) 52(-1.25,-10.525) 53(-0.75,-10.525) 54(-0.25,-10.525) 55(0.25,-10.525) 56(0.75,-10.525) 57(1.25,-10.525) 58(1.75,-10.525) 59(2.25,-10.525) 60(2.75,-10.525) 61(3.25,-10.525) 62(3.75,-10.525) 63(4.25,-10.525) 64(4.75,-10.525) 65(5.25,-10.525) 66(5.75,-10.525) 67(6.25,-10.525) 68(6.75,-10.525) 69(7.25,-10.525) 70(7.75,-10.525) 71(8.25,-10.525) 72(8.75,-10.525) 109(8.75,10.525) 110(8.25,10.525) 111(7.75,10.525) 112(7.25,10.525) 113(6.75,10.525) 114(6.25,10.525) 115(5.75,10.525) 116(5.25,10.525) 117(4.75,10.525) 118(4.25,10.525) 119(3.75,10.525) 120(3.25,10.525) 121(2.75,10.525) 122(2.25,10.525) 123(1.75,10.525) 124(1.25,10.525) 125(0.75,10.525) 126(0.25,10.525) 127(-0.25,10.525) 128(-0.75,10.525) 129(-1.25,10.525) 130(-1.75,10.525) 131(-2.25,10.525) 132(-2.75,10.525) 133(-3.25,10.525) 134(-3.75,10.525) 135(-4.25,10.525) 136(-4.75,10.525) 137(-5.25,10.525) 138(-5.75,10.525) 139(-6.25,10.525) 140(-6.75,10.525) 141(-7.25,10.525) 142(-7.75,10.525) 143(-8.25,10.525) 144(-8.75,10.525)
  rect 4.3x4.3 smd: 145(0,0)
  round 1 smd paste-25.4 mask+0.5: 146(10.7,10.7) 147(-10.7,-10.7)
  silkscreen extent -10.65,-9.35 9.35,9.55, body extent -11,-11.01 11,11, height 1.75
"HEADER 2X4" [mm]
  rect 1.9x1.9 hole 1: 1(0,-2.54)
  round 1.9 hole 1: 2(0,0) 3(2.54,-2.54) 4(2.54,0) 5(5.08,-2.54) 6(5.04,0) 7(7.58,-2.54) 8(7.58,0)
  silkscreen extent -1.27,-3.81 8.85,1.27, body extent -1.27,-3.77 8.91,1.31, height 8.6
"HEADER 2X40" [mm]
  rect 1.9x1.9 hole 0.9: 1(0,0)
  round 1.9 hole 0.9: 2(0,2.54) 3(2.54,0) 4(2.54,2.54) 5(5.08,0) 6(5.08,2.54) 7(7.62,0) 8(7.62,2.54) 9(10.16,0) 10(10.16,2.54) 11(12.7,0) 12(12.7,2.54) 13(15.24,0) 14(15.24,2.54) 15(17.78,0) 16(17.78,2.54) 17(20.32,0) 18(20.32,2.54) 19(22.86,0) 20(22.86,2.54) 21(25.4,0) 22(25.4,2.54) 23(27.94,0) 24(27.94,2.54) 25(30.48,0) 26(30.48,2.54) 27(33.02,0) 28(33.02,2.54) 29(35.56,0) 30(35.56,2.54) 31(38.1,0) 32(38.1,2.54) 33(40.64,0) 34(40.64,2.54) 35(43.18,0) 36(43.18,2.54) 37(45.72,0) 38(45.72,2.54) 39(48.26,0) 40(48.26,2.54) 41(50.8,0) 42(50.8,2.54) 43(53.34,0) 44(53.34,2.54) 45(55.88,0) 46(55.88,2.54) 47(58.42,0) 48(58.42,2.54) 49(60.96,0) 50(60.96,2.54) 51(63.5,0) 52(63.5,2.54) 53(66.04,0) 54(66.04,2.54) 55(68.58,0) 56(68.58,2.54) 57(71.12,0) 58(71.12,2.54) 59(73.66,0) 60(73.66,2.54) 61(76.2,0) 62(76.2,2.54) 63(78.74,0) 64(78.74,2.54) 65(81.28,0) 66(81.28,2.54) 67(83.82,0) 68(83.82,2.54) 69(86.36,0) 70(86.36,2.54) 71(88.9,0) 72(88.9,2.54) 73(91.44,0) 74(91.44,2.54) 75(93.98,0) 76(93.98,2.54) 77(96.52,0) 78(96.52,2.54) 79(99.06,0) 80(99.06,2.54)
  silkscreen extent -1.27,-1.27 100.46,3.81, body extent -1.27,-1.27 100.33,3.81, height 8.64
HSOP8 [mm] "SOIC, 8-Leads, Body 5,0x4,0mm (max), Pitch 1,27mm, IPC Medium Density"
  rect 2.2x0.6 smd: 1(-2.705,1.905)
  oval 2.2x0.6 smd: 2(-2.705,0.635) 3(-2.705,-0.635) 4(-2.705,-1.905) 5(2.705,-1.905) 6(2.705,-0.635) 7(2.705,0.635) 8(2.705,1.905)
  rect 2.4x3.1 smd: 9(0,0)
  silkscreen extent -3.68,-2.4 0.91,2.67, body extent -3.1,-2.49 3.05,2.51, height 1.75
KX-9A [mm]
  rrect30% 1.3x1 smd: 1(-2,-1.2) 2(1.7,-1.2) 3(1.706,1.025) 4(-1.994,1.025)
  silkscreen extent -3.7,-2.8 2.7,1.9, body extent -2.6,-1.7 2.4,1.5, height 1.01
KXO-97 [mm]
  rect 1.8x2 smd: 1(-2.54,-2.1)
  rrect50% 1.8x2 smd: 2(2.54,-2.1) 3(2.54,2.1) 4(-2.54,2.1)
  silkscreen extent -4.66,-4.49 3.94,3.56, body extent -3.5,-2.54 3.5,2.54, height 1.81
LED0805W [mm]
  rrect30% 1.05x1.45 smd: A(-1.025,0) K(1.025,0)
  silkscreen extent -0.25,-0.4 0.25,0.4, body extent -1.04,-0.63 1.06,0.63, height 0.75
M3 [mm]
  round 6 hole 3.2: 0(0.003,0.031)
  body extent -3,-3 3,3, height 0.1
"MKDSN 1.5/4-5.08" [mm]
  round 2.4 hole 1.4: 1(0,0) 2(5.08,0) 3(10.16,0) 4(15.24,0)
  silkscreen extent -3.05,-4.06 17.78,4.06, body extent -3.08,-4.06 17.81,4.04, height 10
PQFP240_N [mm] "Shrink QFP, 240-Leads, Body 32x32mm, Pitch 0.5mm, IPC Medium Density"
  oval 1.8x0.3 smd: 1(-16.85,14.75) 2(-16.85,14.25) 3(-16.85,13.75) 4(-16.85,13.25) 5(-16.85,12.75) 6(-16.85,12.25) 7(-16.85,11.75) 8(-16.85,11.25) 9(-16.85,10.75) 10(-16.85,10.25) 11(-16.85,9.75) 12(-16.85,9.25) 13(-16.85,8.75) 14(-16.85,8.25) 15(-16.85,7.75) 16(-16.85,7.25) 17(-16.85,6.75) 18(-16.85,6.25) 19(-16.85,5.75) 20(-16.85,5.25) 21(-16.85,4.75) 22(-16.85,4.25) 23(-16.85,3.75) 24(-16.85,3.25) 25(-16.85,2.75) 26(-16.85,2.25) 27(-16.85,1.75) 28(-16.85,1.25) 29(-16.85,0.75) 30(-16.85,0.25) 31(-16.85,-0.25) 32(-16.85,-0.75) 33(-16.85,-1.25) 34(-16.85,-1.75) 35(-16.85,-2.25) 36(-16.85,-2.75) 37(-16.85,-3.25) 38(-16.85,-3.75) 39(-16.85,-4.25) 40(-16.85,-4.75) 41(-16.85,-5.25) 42(-16.85,-5.75) 43(-16.85,-6.25) 44(-16.85,-6.75) 45(-16.85,-7.25) 46(-16.85,-7.75) 47(-16.85,-8.25) 48(-16.85,-8.75) 49(-16.85,-9.25) 50(-16.85,-9.75) 51(-16.85,-10.25) 52(-16.85,-10.75) 53(-16.85,-11.25) 54(-16.85,-11.75) 55(-16.85,-12.25) 56(-16.85,-12.75) 57(-16.85,-13.25) 58(-16.85,-13.75) 59(-16.85,-14.25) 60(-16.85,-14.75) 121(16.85,-14.75) 122(16.85,-14.25) 123(16.85,-13.75) 124(16.85,-13.25) 125(16.85,-12.75) 126(16.85,-12.25) 127(16.85,-11.75) 128(16.85,-11.25) 129(16.85,-10.75) 130(16.85,-10.25) 131(16.85,-9.75) 132(16.85,-9.25) 133(16.85,-8.75) 134(16.85,-8.25) 135(16.85,-7.75) 136(16.85,-7.25) 137(16.85,-6.75) 138(16.85,-6.25) 139(16.85,-5.75) 140(16.85,-5.25) 141(16.85,-4.75) 142(16.85,-4.25) 143(16.85,-3.75) 144(16.85,-3.25) 145(16.85,-2.75) 146(16.85,-2.25) 147(16.85,-1.75) 148(16.85,-1.25) 149(16.85,-0.75) 150(16.85,-0.25) 151(16.85,0.25) 152(16.85,0.75) 153(16.85,1.25) 154(16.85,1.75) 155(16.85,2.25) 156(16.85,2.75) 157(16.85,3.25) 158(16.85,3.75) 159(16.85,4.25) 160(16.85,4.75) 161(16.85,5.25) 162(16.85,5.75) 163(16.85,6.25) 164(16.85,6.75) 165(16.85,7.25) 166(16.85,7.75) 167(16.85,8.25) 168(16.85,8.75) 169(16.85,9.25) 170(16.85,9.75) 171(16.85,10.25) 172(16.85,10.75) 173(16.85,11.25) 174(16.85,11.75) 175(16.85,12.25) 176(16.85,12.75) 177(16.85,13.25) 178(16.85,13.75) 179(16.85,14.25) 180(16.85,14.75)
  oval 0.3x1.8 smd: 61(-14.75,-16.85) 62(-14.25,-16.85) 63(-13.75,-16.85) 64(-13.25,-16.85) 65(-12.75,-16.85) 66(-12.25,-16.85) 67(-11.75,-16.85) 68(-11.25,-16.85) 69(-10.75,-16.85) 70(-10.25,-16.85) 71(-9.75,-16.85) 72(-9.25,-16.85) 73(-8.75,-16.85) 74(-8.25,-16.85) 75(-7.75,-16.85) 76(-7.25,-16.85) 77(-6.75,-16.85) 78(-6.25,-16.85) 79(-5.75,-16.85) 80(-5.25,-16.85) 81(-4.75,-16.85) 82(-4.25,-16.85) 83(-3.75,-16.85) 84(-3.25,-16.85) 85(-2.75,-16.85) 86(-2.25,-16.85) 87(-1.75,-16.85) 88(-1.25,-16.85) 89(-0.75,-16.85) 90(-0.25,-16.85) 91(0.25,-16.85) 92(0.75,-16.85) 93(1.25,-16.85) 94(1.75,-16.85) 95(2.25,-16.85) 96(2.75,-16.85) 97(3.25,-16.85) 98(3.75,-16.85) 99(4.25,-16.85) 100(4.75,-16.85) 101(5.25,-16.85) 102(5.75,-16.85) 103(6.25,-16.85) 104(6.75,-16.85) 105(7.25,-16.85) 106(7.75,-16.85) 107(8.25,-16.85) 108(8.75,-16.85) 109(9.25,-16.85) 110(9.75,-16.85) 111(10.25,-16.85) 112(10.75,-16.85) 113(11.25,-16.85) 114(11.75,-16.85) 115(12.25,-16.85) 116(12.75,-16.85) 117(13.25,-16.85) 118(13.75,-16.85) 119(14.25,-16.85) 120(14.75,-16.85) 181(14.75,16.85) 182(14.25,16.85) 183(13.75,16.85) 184(13.25,16.85) 185(12.75,16.85) 186(12.25,16.85) 187(11.75,16.85) 188(11.25,16.85) 189(10.75,16.85) 190(10.25,16.85) 191(9.75,16.85) 192(9.25,16.85) 193(8.75,16.85) 194(8.25,16.85) 195(7.75,16.85) 196(7.25,16.85) 197(6.75,16.85) 198(6.25,16.85) 199(5.75,16.85) 200(5.25,16.85) 201(4.75,16.85) 202(4.25,16.85) 203(3.75,16.85) 204(3.25,16.85) 205(2.75,16.85) 206(2.25,16.85) 207(1.75,16.85) 208(1.25,16.85) 209(0.75,16.85) 210(0.25,16.85) 211(-0.25,16.85) 212(-0.75,16.85) 213(-1.25,16.85) 214(-1.75,16.85) 215(-2.25,16.85) 216(-2.75,16.85) 217(-3.25,16.85) 218(-3.75,16.85) 219(-4.25,16.85) 220(-4.75,16.85) 221(-5.25,16.85) 222(-5.75,16.85) 223(-6.25,16.85) 224(-6.75,16.85) 225(-7.25,16.85) 226(-7.75,16.85) 227(-8.25,16.85) 228(-8.75,16.85) 229(-9.25,16.85) 230(-9.75,16.85) 231(-10.25,16.85) 232(-10.75,16.85) 233(-11.25,16.85) 234(-11.75,16.85) 235(-12.25,16.85) 236(-12.75,16.85) 237(-13.25,16.85) 238(-13.75,16.85) 239(-14.25,16.85) 240(-14.75,16.85)
  silkscreen extent -16.98,-15.55 15.55,15.57, body extent -17.35,-17.3 17.25,17.3, height 3.6
R0603 [mm]
  rrect30% 1x1 smd: 1(-0.8,0) 2(0.8,0)
  silkscreen extent -0.1,-0.4 0.1,0.4, body extent -0.8,-0.4 0.8,0.4, height 0.5
R0805 [mm]
  rrect30% 1.15x1.45 smd: 1(-1.025,0) 2(1.025,0)
  silkscreen extent -0.05,-0.63 0.05,0.63, body extent -1,-0.62 1,0.64, height 0.41
SC-70 [mm]
  oval 0.7x0.4 smd: 1(-0.95,0.65) 2(-0.95,-0.65) 3(0.95,0)
  silkscreen extent -0.32,-1 0.25,0.93, body extent -1.07,-1 1.07,1, height 1.15
SO-16W [mm]
  oval 0.75x2.05 smd: 1(-4.445,-4.65) 2(-3.175,-4.65) 3(-1.905,-4.65) 4(-0.635,-4.65) 5(0.635,-4.65) 6(1.905,-4.65) 7(3.175,-4.65) 8(4.445,-4.65) 9(4.445,4.65) 10(3.175,4.65) 11(1.905,4.65) 12(0.635,4.65) 13(-0.635,4.65) 14(-1.905,4.65) 15(-3.175,4.65) 16(-4.445,4.65)
  silkscreen extent -5.25,-3.25 5.25,3.25, body extent -5.13,-5.13 5.17,5.17, height 2.65
SOD-80 [mm]
  rrect30% 1.43x1.9 smd: 1(-1.6,0) 2(1.7,0)
  silkscreen extent -0.5,-0.87 0.6,0.81, body extent -1.75,-0.8 1.95,0.8, height 1.6
SOT-23-6 [mm]
  oval 1.35x0.6 smd: 1(-1.25,0.95) 2(-1.25,0) 3(-1.25,-0.95) 4(1.25,-0.95) 5(1.25,0) 6(1.25,0.95)
  silkscreen extent -2.81,-1.52 2.16,1.52, body extent -1.5,-1.5 1.5,1.5, height 1.5
SWT-2/5 [mm]
  round 1.8 hole 1: 1(-3.2,2.214) 1(3.3,2.214) 2(-3.2,-2.286) 2(3.3,-2.286)
  silkscreen extent -3.9,-3.29 3.9,3.11, body extent -4.05,-3.09 4.05,2.93, height 5.1

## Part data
C1 C2 C3 C4 C5 C6 C7 C8 C9 C10 C11 C12 C13 C14 C15 C16 C17 C18 C19 C20 C21 C22 C23 C24 C25 C26 C27 C28 C29 C30 C31 C32 C45 C46 C47 C48 C49 C50 C69 C70 C71 C72 C73 C74 C75 C76 C77 C78 C79 C80 C81 C82: library part "100нФ 50 В", "конденсатор керамический SMD"
C33 C34 C35 C42 C43 C44 C51 C52 C53 C54 C55 C56: library part "22 мкФ 16 В", "конденсатор керамический"
C36A C36B C37A C37B C38A C38B C39A C39B C40A C40B C41A C41B C58 C64 C67 C68 C85 C86 C87 C88 C89: library part "470нФ 50 В", "конденсатор керамический SMD"
C57 C59 C61 C62 C63 C66: "конденсатор электролитический SMD"
C60 C65 C90 C91 C92 C93: library part "10нФ 50 В", "конденсатор керамический SMD"
C83 C84: library part "27пФ  50В", "конденсатор керамический"
DA1 DA2 DA3 DA5: "1 MHz, 2.0 A Synchronous  Buck Regulator"
DA4: "STEP-DOWN 500kHz"
DD1: "Cyclone III Family FPGA, 160 I/O Pins, 4 PLLs, 240-Pin PQFP, Speed Grade 8, Commercial Grade, Pb-Free"
DD2: "EPCS16 Series, In-system programmable 3.3V serial configuration device, 8-Pin SOIC, 4-Megabit, Industrial Grade"
DD3: "Cyclone III Family FPGA, 94 I/O Pins, 4 PLLs, 144-Pin EQFP, Speed Grade 8, Commercial Grade"
DD13: "2-х разрядный инвертор"
JA JB PA PB: "Штырьки на плату шаг 2,54 мм"
K1 K2 K3 K4: library part SWT-2/5, "тактовая кнопка"
L1 L2 L4 L5 L6: "катушка индуктивности"
LED1 LED2 LED3 LED4 LED5 LED6: "белый светодиод"
R1 R2 R3 R4 R6 R7 R8 R9 R10 R11 R12 R13 R14 R15 R16 R17 R18 R19 R20 R21 R22 R23 R24 R25 R26 R27 R28 R29 R34 R35: "резистор постоянный"
R5: "Массив резисторов"
S1: "DIP переключатель на 4 позиции"
VD1 VD2 VD3 VD4 VD5: "High-Current Density Schottky Rectifier"
VD6A VD6B VD7A VD7B VD8A VD8B VD9A VD9B VD10A VD10B VD11A VD11B VD12A VD12B VD13A VD13B VD14A VD14B VD15A VD15B VD16A VD16B VD17A VD17B VD18A VD18B VD19A VD19B VD20A VD20B VD21A VD21B VD22A VD22B VD23A VD23B VD24A VD24B VD25A VD25B VD26A VD26B VD27A VD27B VD28A VD28B VD29A VD29B VD30A VD30B VD31A VD31B VD32A VD32B VD33A VD33B VD34A VD34B VD35A VD35B VD36A VD36B VD37A VD37B VD38A VD38B VD39A VD39B VD40A VD40B VD41A VD41B VD42A VD42B VD43A VD43B VD44A VD44B VD45A VD45B VD46A VD46B VD47A VD47B VD48A VD48B VD49A VD49B VD50A VD50B VD51A VD51B VD52A VD52B VD53A VD53B VD54A VD54B VD55A VD55B VD56A VD56B VD57A VD57B VD58A VD58B VD59A VD59B VD60A VD60B VD61A VD61B VD62A VD62B VD63A VD63B VD64A VD64B VD65A VD65B: "два диода Шоттки"
VD66 VD67: "Стабилитрон 0,5Вт"
X1 X2: "вилка IDC на плату прямая"
ZQ1: "Кварцевый генератор"
ZQ3: "Кварцевый резонатор"

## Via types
v1: diameter 0.6, hole 0.3, Top Layer to Bottom Layer, tented both sides, 413 vias
v2: diameter 1.4, hole 0.7, Top Layer to Bottom Layer, 32 vias
v3: diameter 1, hole 0.5, Top Layer to Bottom Layer, tented both sides, 19 vias
v4: diameter 0.66, hole 0.33, Top Layer to Bottom Layer, tented top, 16 vias
v5: diameter 0.6, hole 0.3, Top Layer to Bottom Layer, 8 vias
